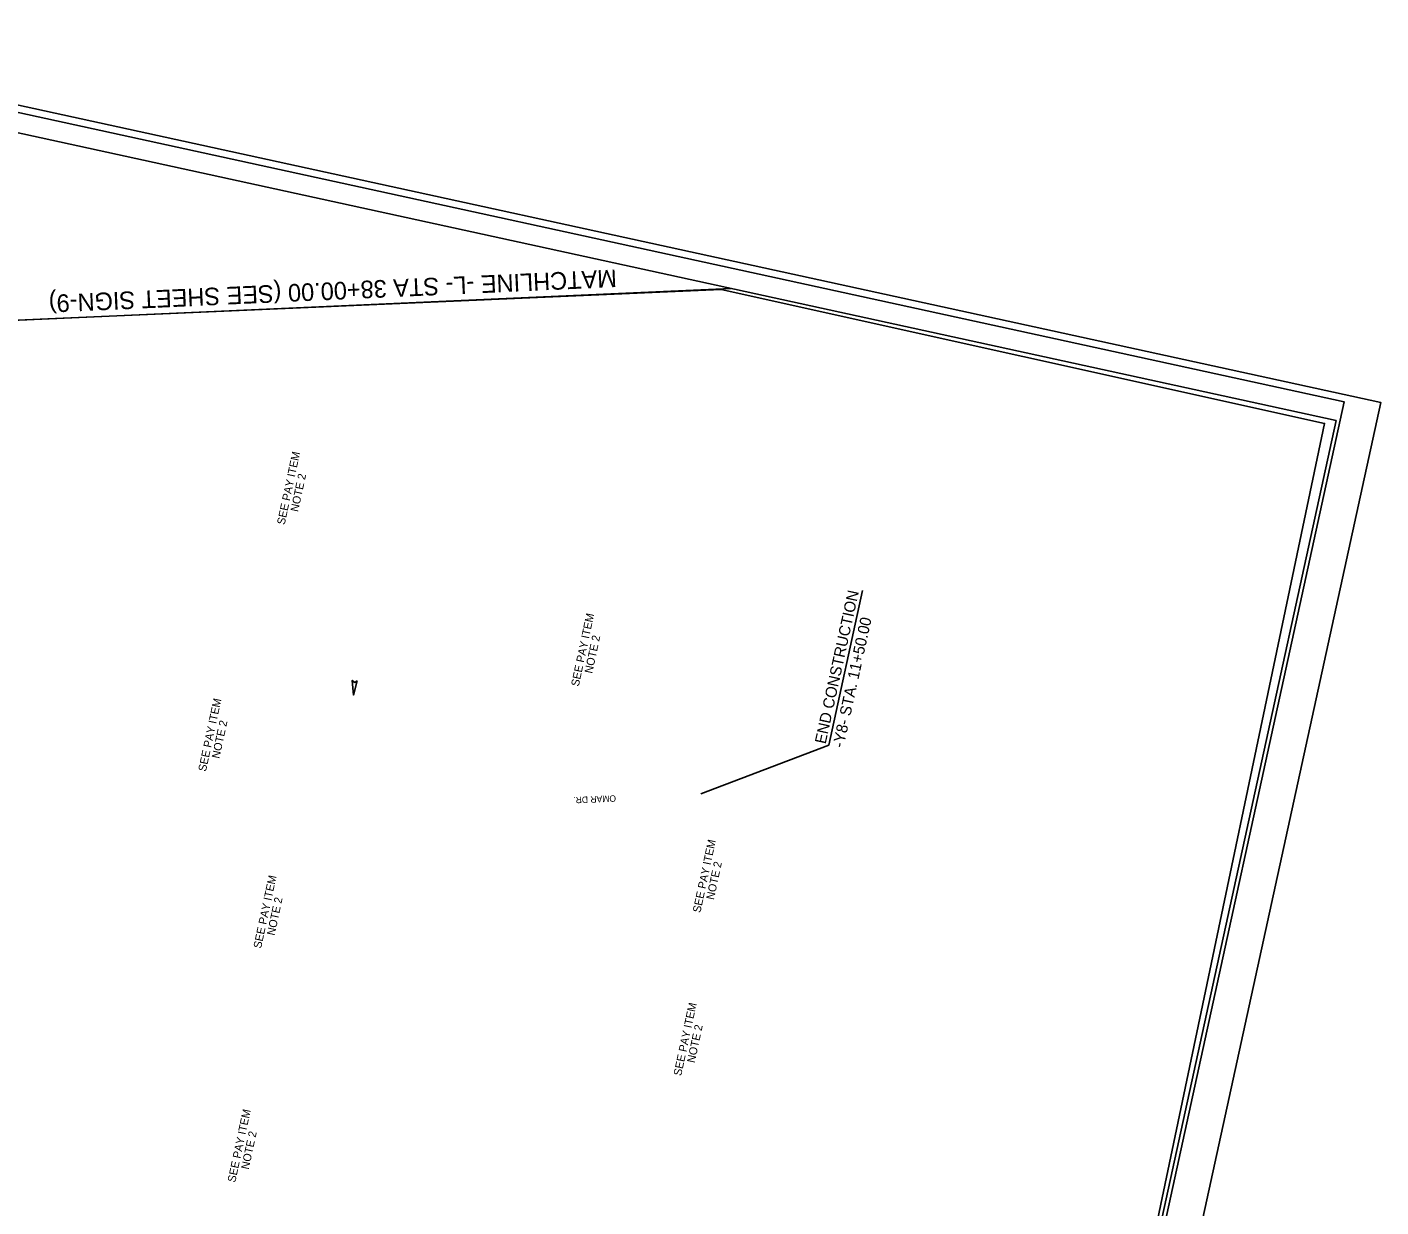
# Model space of a CAD drawing. Extents: x 1615829 to 1617263, y 900664 to 902544.
# Drawn here: x 1616417 to 1617263, y 901807 to 902544 of the extents above; entities that cross this region are included whole.
import ezdxf

# ---------------------------------------------------------------- set-up
doc = ezdxf.new("R2010")
doc.units = 0
for name, color, linetype in [('Default', 7, 'Continuous'), ('Exist PHM ROW shape', 7, 'Continuous'), ('Prop Conc Drive Radius Type', 7, 'Continuous'), ('Prop Conc Island Cover', 7, 'Continuous'), ('Prop Dimension Text', 7, 'Continuous'), ('Prop Lane Arrow CELL', 7, 'Continuous'), ('Prop PHM Concrete Structures Shape', 7, 'Continuous'), ('Prop PHM ROW', 7, 'Continuous'), ('Prop Shade Medium', 7, 'Continuous'), ('Prop Terminator CELL', 7, 'Continuous'), ('Scratch_Level_2', 7, 'Continuous')]:
    doc.layers.add(name, color=color, linetype=linetype)

msp = doc.modelspace()

# ---------------------------------------------------------------- linework, layer by layer
at = {"layer": 'Exist PHM ROW shape'}
msp.add_line((1616938.79, 902191.77), (1616917.7, 902095.15), dxfattribs=at)
at = {"layer": 'Prop Conc Drive Radius Type'}
msp.add_lwpolyline([(1616850.42, 902379.94), (1617227.49, 902296.2), (1617121.36, 901790.43), (1617088.18, 901641.75), (1617042.44, 901522.26), (1617032.35, 901430.63), (1617021.35, 901334.38), (1616928.77, 900896.77), (1615902.83, 901120.28), (1615974.27, 901386.7), (1616087.67, 901888.92), (1616145.49, 901879.24), (1616184.12, 901827.49), (1616138.37, 901614.97), (1616150.59, 901618.07), (1616181.32, 901620.66), (1616299.19, 901764.2), (1616120.07, 901933.32), (1616161.35, 902112.51), (1616179.69, 902310.42), (1616356.27, 902284.95), (1616372.44, 902359.01)], close=True, dxfattribs=at)
at = {"layer": 'Prop Dimension Text'}
msp.add_line((1616372.44, 902359.01), (1616856.51, 902380.51), dxfattribs=at)
at = {"layer": 'Prop PHM Concrete Structures Shape'}
msp.add_lwpolyline([(1616208.79, 902521.9), (1615888.89, 901056.41), (1616914.73, 900832.48), (1617234.63, 902297.97)], close=True, dxfattribs=at)
at = {"layer": 'Prop PHM ROW'}
msp.add_line((1616917.7, 902095.15), (1616837.69, 902064.8), dxfattribs=at)
at = {"layer": 'Prop Shade Medium'}
msp.add_lwpolyline([(1616187.99, 902543.84), (1615828.85, 900898.58), (1616903.54, 900663.99), (1617262.68, 902309.25)], close=True, dxfattribs=at)
at = {"layer": 'Prop Terminator CELL'}
msp.add_lwpolyline([(1616623.17, 902135.32), (1616620.88, 902126.48), (1616620.03, 902135.63), (1616621.53, 902134.35)], close=True, dxfattribs=at)
msp.add_lwpolyline([(1616623.17, 902135.32), (1616620.88, 902126.48), (1616620.03, 902135.63), (1616621.53, 902134.35)], close=True, dxfattribs=at)
at = {"layer": 'Scratch_Level_2'}
msp.add_lwpolyline([(1616208.96, 902534.66), (1615853.55, 900906.5), (1616884.38, 900681.48), (1617239.79, 902309.64)], close=True, dxfattribs=at)

# ---------------------------------------------------------------- texts
at = {"layer": 'Default'}
for s, p in [('SEE PAY ITEM', (1616577.77, 902232.58)), ('NOTE 2', (1616586.2, 902240.66)), ('SEE PAY ITEM', (1616761.51, 902131.59)), ('NOTE 2', (1616769.94, 902139.66)), ('SEE PAY ITEM', (1616528.6, 902078.41)), ('NOTE 2', (1616537.03, 902086.49)), ('SEE PAY ITEM', (1616837.51, 901990.18)), ('NOTE 2', (1616845.94, 901998.26)), ('SEE PAY ITEM', (1616563.05, 901967.88)), ('NOTE 2', (1616571.48, 901975.96)), ('SEE PAY ITEM', (1616825.53, 901888.26)), ('NOTE 2', (1616833.96, 901896.34)), ('SEE PAY ITEM', (1616546.92, 901821.7)), ('NOTE 2', (1616555.35, 901829.78))]:
    msp.add_text(s, height=5, rotation=77.92233, dxfattribs=at).set_placement(p)
at = {"layer": 'Exist PHM ROW shape'}
for s, p in [('END CONSTRUCTION', (1616915.74, 902095.57)), ('-Y8- STA. 11+50.00', (1616926.86, 902093.15))]:
    msp.add_text(s, height=7, rotation=77.68623, dxfattribs=at).set_placement(p)
at = {"layer": 'Prop Conc Island Cover'}
msp.add_text('OMAR DR.', height=4, rotation=182.39753, dxfattribs=at).set_placement((1616784.73, 902063.89))
at = {"layer": 'Prop Lane Arrow CELL'}
msp.add_text('MATCHLINE -L- STA 38+00.00 (SEE SHEET SIGN-9)', height=11, rotation=182.58128, dxfattribs=at).set_placement((1616785.02, 902392.43))

doc.saveas('drawing.dxf')
